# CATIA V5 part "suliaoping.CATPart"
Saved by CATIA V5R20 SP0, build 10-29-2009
Part number: 熟料瓶
Material "Gravel 1": density 2250 kg/m3, Young's modulus 5e+10 Pa, Poisson ratio 0.25
Bounding box of the stored display mesh (mm): x -25 to 25, y -25 to 27, z 0 to 110
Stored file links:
  G:\suliaoping.CATPart
  D:\CATIA VR20\win_b64\startup\materials\Catalog.CATMaterial
  D:\CATIA VR20\win_b64\startup\materials\pebble.jpg
  D:\CATIA VR20\win_b64\startup\materials\DS_star.jpg
  D:\CATIA VR20\win_b64\startup\materials\birch.jpg
  D:\CATIA VR20\win_b64\startup\materials\gravel_1.jpg
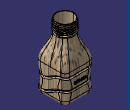
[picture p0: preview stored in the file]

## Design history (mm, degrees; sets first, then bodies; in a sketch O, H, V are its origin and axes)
Body1 (main body), material "无"
  Sketch1 on xy-plane, origin (0, 0, 0), H (1, 0, 0), V (0, 1, 0)
    line L1 (25, 25) -> (25, -25)
    line L2 (25, -25) -> (-25, -25)
    line L3 (-25, -25) -> (-25, 25)
    line L4 (-25, 25) -> (25, 25)
    length L1 = 50
    length L4 = 50
    vertical: L1 V, L3 V
    horizontal: L2 H, L4 H
    equidistance: L1 L3 O, L2 L4 O
  Pad1: profile Sketch1, direction (0, 0, 1), length 50
  Fillet1: on edge [face of Pad1 from Sketch1.L1 | face of Pad1 from Sketch1.L2]; edge [face of Pad1 from Sketch1.L4 | face of Pad1 from Sketch1.L1]; edge [face of Pad1 from Sketch1.L3 | face of Pad1 from Sketch1.L4]; edge [face of Pad1 from Sketch1.L2 | face of Pad1 from Sketch1.L3]
  Fillet2: on edge [start face of Pad1 | face of Pad1 from Sketch1.L2]
  Plane1: type Offset, RefPlane end face of Pad1, Offset 40, reversed
  Sketch2 on Plane1, origin (0, 0, 90), H (1, 0, 0), V (0, -1, 0)
    circle A1 centre (0, 0) radius 15
    radius A1 = 15
  Pad2: profile Sketch2, direction (0, 0, 1), length 20
  Sketch3 on Plane1, origin (0, 0, 90), H (1, 0, 0), V (0, -1, 0)
    point P1 (15, 0)
    distance P1 V = 15
    coincidence: P1 H
  Sketch4 on end face of Pad1, origin (0, 0, 50), H (1, 0, 0), V (0, 1, 0)
    point P1 (25, 0)
    distance P1 V = 25
  Loft1: solid, Sections ({boundary Boundary {extract ExtractElem start face of Pad2}}; {boundary Boundary {extract ExtractElem end face of Pad1}}), StartFace start face of Pad2, EndFace end face of Pad1
  Sketch5 on face of Pad1 from Sketch1.L3, origin (-25, 0, 0), H (0, -1, 0), V (0, 0, 1)
    spline S1 through (-40, 10) (-10, 20) (10, 10) (30, 20)
    spline S2 through (-40, 30) (-10, 40) (10, 30) (30, 40)
  Extrude1: Element1 Sketch5, Lim1 60, Lim2 60
  MultiSel1: CommonCtxFeats ({extract ExtractElem face of Fillet1}; {extract ExtractElem face of Pad1 from Sketch1.L1}; {extract ExtractElem face of Fillet1}; {extract ExtractElem face of Pad1 from Sketch1.L4}; {extract ExtractElem face of Fillet1}; {extract ExtractElem face of Pad1 from Sketch1.L3}; {extract ExtractElem face of Fillet1}; {extract ExtractElem face of Pad1 from Sketch1.L2})
  DatumCurve1 to DatumCurve8
  Line1: stored without definition
  Line2: stored without definition
  DatumCurve9 to DatumCurve11
  Line3: stored without definition
  Line4: stored without definition
  DatumCurve12
  DatumCurve13
  Join1: Elements (Line3; DatumCurve12; DatumCurve7; DatumCurve5; Line1; DatumCurve10; DatumCurve1; DatumCurve3)
  Join2: Elements (DatumCurve13; DatumCurve9; DatumCurve6; Line4; Line2; DatumCurve11; DatumCurve2; DatumCurve4)
  Plane2: type Normal, Curve Join2, RefPoint vertex of MultiSel1
  Plane3: type Normal, Curve Join1, RefPoint vertex of MultiSel1
  Circle1: type CtrRad, Start 0, End 180, Center vertex of MultiSel1, Support Plane2, Radius 2, FirstDirection (1, 0, 0)
  Circle2: type CtrRad, Start 0, End 180, Center vertex of MultiSel1, Support Plane3, Radius 2, FirstDirection (0, -1, 0)
  Slot1: profile Circle1, centre curve Join2
  Slot2: profile Circle2, centre curve Join1
  Shell1: IntOffset 1, Face end face of Pad2, ExtOffset 0
  Point1: (0, 0, 2), relative to Sketch3
  Helix1: Direction Z axis, RefPoint Point1, Pitch 3, Height 16, TaperAngle 0
  Point2: type OnCurve, Support Helix1, RefPoint vertex of Helix1, Length 5
  Point3: type OnCurve, Support Helix1, RefPoint Point1, Length 5
  Point4: (-5, 0, 0), relative to Point1
  Point5: (0, -5, 0), relative to vertex of Helix1
  Line5: type PtPt, FirstPoint vertex of Helix1, SecondPoint Point5
  Line6: type PtPt, FirstPoint Point1, SecondPoint Point4
  Connect1: Curve1 Line6, Point1 Point4, Tension1 1, Curve2 Helix1, Point2 Point3, Tension2 1
  Point6: stored without definition
  Point7: stored without definition
  Connect2: Curve1 Line5, Point1 Point5, Tension1 1, Curve2 Connect1, Point2 Point7, Tension2 1
  Plane4: type Normal, Curve Connect2, RefPoint Point4
  Circle3: type CtrRad, Start 0, End 180, Center Point4, Support Plane4, Radius 1, FirstDirection (0, 1, 0)
  Rib1: profile Circle3, centre curve Connect2
  Body2
    Sketch6 on Plane1, origin (0, 0, 90), H (1, 0, 0), V (0, -1, 0)
      circle A1 centre (0, 0) radius 14
      polyline C1
      polyline C2
      polyline C3
      polyline C4
      polyline C5
      polyline C6
      polyline C7
      polyline C8
      polyline C9
      polyline C10
      polyline C11
      radius A1 = 14
    Pad3: profile Sketch6, direction (0, 0, 1), length 20
  Remove1: tool Body2
  Sketch7 on face of Pad1 from Sketch1.L4, origin (0, 25, 0), H (-1, 0, 0), V (0, 0, 1)
    polyline C1
    polyline C2
    polyline C3
    polyline C4
    polyline C5
    polyline C6
    polyline C7
    polyline C8
    polyline C9
    polyline C10
    polyline C11
  Pad4: profile Sketch7, direction (0, 1, 0), length 2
